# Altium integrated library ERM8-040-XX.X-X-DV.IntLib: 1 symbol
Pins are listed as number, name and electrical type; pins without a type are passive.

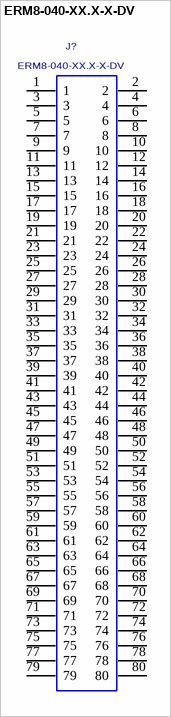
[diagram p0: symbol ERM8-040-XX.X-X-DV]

## ERM8-040-XX.X-X-DV
designator J?
0.8mm Edge Rate Terminal Assembly, Double Vertical Row, 40 Position, 0.8mm Pitch; MANUFACTURER: SAMTEC
footprint ERM8-040-XX.X-X-DV
pins: 1, 2, 3, 4, 5, 6, 7, 8, 9, 10, 11, 12, 13, 14, 15, 16, 17, 18, 19, 20, 21, 22, 23, 24, 25, 26, 27, 28, 29, 30, 31, 32, 33, 34, 35, 36, 37, 38, 39, 40, 41, 42, 43, 44, 45, 46, 47, 48, 49, 50, 51, 52, 53, 54, 55, 56, 57, 58, 59, 60, 61, 62, 63, 64, 65, 66, 67, 68, 69, 70, 71, 72, 73, 74, 75, 76, 77, 78, 79, 80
